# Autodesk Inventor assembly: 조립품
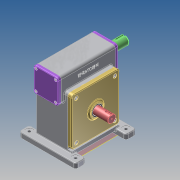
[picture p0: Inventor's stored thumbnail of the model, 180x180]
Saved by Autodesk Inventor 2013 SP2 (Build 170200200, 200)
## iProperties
Created: 2025-06
Part Number: 조립품
Document SubType Name: Assembly
Designer: i
Author: i
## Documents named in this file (14)
- C:\Users\i\Desktop\750603V1017\조립품.iam
- C:\Users\i\Desktop\750603V1017\본체.ipt
- C:\Users\i\Desktop\750603V1017\앞커버.ipt
- C:\Users\i\Desktop\750603V1017\오일 실 30 42 7.ipt
- C:\Users\i\Desktop\750603V1017\오일 실 35 55 11.ipt
- C:\Users\i\Desktop\750603V1017\웜 샤프트.ipt
- C:\Users\i\Desktop\750603V1017\웜 휠 커버.ipt
- C:\Users\i\Desktop\750603V1017\웜 휠.ipt
- C:\Users\i\Desktop\750603V1017\6각 구멍붙이 볼트 M6x12.ipt
- C:\Users\i\Desktop\750603V1017\6각 구멍붙이 볼트 M8x20.ipt
- C:\Users\i\Desktop\750603V1017\깊은 홈 볼 베어링 6206.ipt
- C:\Users\i\Desktop\750603V1017\깊은 홈 볼 베어링 6209.ipt
- C:\Users\i\Desktop\750603V1017\뒷커버.ipt
- C:\Users\i\Desktop\750603V1017\6각 구멍붙이 볼트 M6x12_MIR.ipt
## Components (12 placed, 3 different names)
1. 6각 구멍붙이 볼트 M6x12_MIR:1
2. 6각 구멍붙이 볼트 M6x12_MIR:2
3. 6각 구멍붙이 볼트 M6x12_MIR:3
4. 6각 구멍붙이 볼트 M6x12_MIR:4
5. 6각 구멍붙이 볼트 M8x20:1
6. 6각 구멍붙이 볼트 M8x20:2
7. 6각 구멍붙이 볼트 M8x20:3
8. 6각 구멍붙이 볼트 M8x20:4
9. 6각 구멍붙이 볼트 M6x12:1
10. 6각 구멍붙이 볼트 M6x12:2
11. 6각 구멍붙이 볼트 M6x12:3
12. 6각 구멍붙이 볼트 M6x12:4
